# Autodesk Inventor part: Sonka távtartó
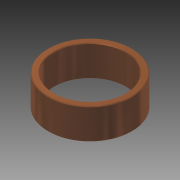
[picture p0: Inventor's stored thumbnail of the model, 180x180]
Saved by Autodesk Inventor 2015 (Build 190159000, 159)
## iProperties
Created: 2013-02
Part Number: Sonka távtartó
Material: Generic
Document SubType Name: Modeling
Designer: Marci
Density: 1 g/cm^3
Appearance: Copper - Satin
Author: Marci
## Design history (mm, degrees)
sketch "Sketch1"
  geometry: C1 r 12.75 at (0, 0); C2 r 15 at (0, 0); 1 further point
  constraints: 2 centre point, 2 coincident
  dimensions: "d0" = 25.5 diameter of C1; "d1" = 30 diameter of C2
extrude "Extrusion1" new body sketch "Sketch1" distance "d2" = 11; taper "d3" = 0 deg
chamfer "Chamfer1" distance "d4" = 0.25; stored, may be unused: second distance "d5" = 2, angle "d6" = 45 deg
body "Solid1"
